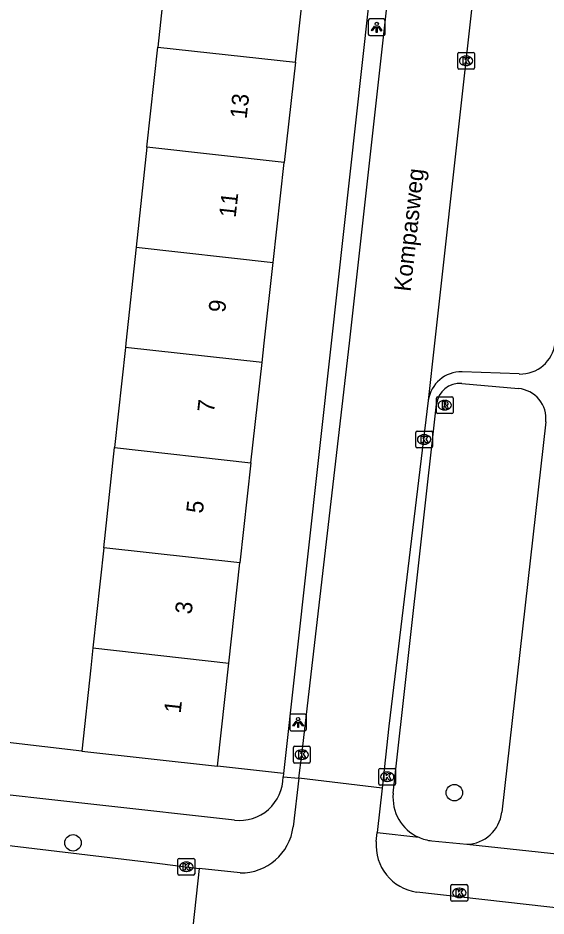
# Model space of a CAD drawing. Extents: x 161928 to 163055, y 386475 to 387428.
# Drawn here: x 162354.3 to 162385.7, y 386965.9 to 387019.4 of the extents above; entities that cross this region are included whole.
import ezdxf

# ---------------------------------------------------------------- set-up
doc = ezdxf.new("R2010")
doc.units = 0
for name, color, linetype in [('IMGEO_Boom', 7, 'Continuous'), ('IMGEO_Groenvoorziening', 7, 'Continuous'), ('IMGEO_Kolk', 7, 'Continuous'), ('IMGEO_Lichtpunt', 7, 'Continuous'), ('IMGEO_Openbare_ruimte_label', 7, 'Continuous'), ('IMGEO_Pand', 7, 'Continuous'), ('IMGEO_Pand_nummerreeks', 7, 'Continuous'), ('IMGEO_Rijbaan_lokaal_gesloten', 7, 'Continuous'), ('IMGEO_Rijbaan_lokaal_open', 7, 'Continuous'), ('IMGEO_Rioolput', 7, 'Continuous'), ('IMGEO_Voetpad_open', 7, 'Continuous')]:
    doc.layers.add(name, color=color, linetype=linetype)

msp = doc.modelspace()

# ---------------------------------------------------------------- linework, layer by layer
at = {"layer": 'IMGEO_Boom'}
for centre in [(162380.28, 386973.215), (162357.553, 386970.228)]:
    msp.add_circle(centre, 0.489, dxfattribs=at)
at = {"layer": 'IMGEO_Groenvoorziening'}
for points in [[(162358.078, 386975.691), (162351.103, 386976.499)], [(162370.099, 386974.362), (162366.155, 386974.797)]]:
    msp.add_lwpolyline(points, dxfattribs=at)
at = {"layer": 'IMGEO_Kolk'}
for p, q in [((162380.479, 387016.386), (162380.479, 387017.238)), ((162380.554, 387017.312), (162381.406, 387017.312)), ((162380.967, 387017.092), (162380.992, 387017.092)), ((162381.48, 387017.238), (162381.48, 387016.386)), ((162380.99, 387016.532), (162380.965, 387016.532)), ((162381.406, 387016.312), (162380.554, 387016.312)), ((162377.979, 386993.828), (162377.979, 386994.68)), ((162378.054, 386994.754), (162378.906, 386994.754)), ((162378.98, 386994.68), (162378.98, 386993.828)), ((162378.467, 386994.534), (162378.492, 386994.534)), ((162378.906, 386993.754), (162378.054, 386993.754)), ((162378.49, 386993.974), (162378.465, 386993.974)), ((162370.685, 386975.054), (162370.685, 386975.906)), ((162370.76, 386975.98), (162371.612, 386975.98)), ((162371.686, 386975.906), (162371.686, 386975.054)), ((162371.173, 386975.76), (162371.198, 386975.76)), ((162371.612, 386974.98), (162370.76, 386974.98)), ((162371.196, 386975.2), (162371.171, 386975.2)), ((162375.778, 386973.739), (162375.778, 386974.591)), ((162375.853, 386974.665), (162376.705, 386974.665)), ((162376.266, 386974.445), (162376.291, 386974.445)), ((162376.779, 386974.591), (162376.779, 386973.739)), ((162376.289, 386973.885), (162376.264, 386973.885)), ((162376.705, 386973.665), (162375.853, 386973.665)), ((162363.802, 386968.377), (162363.802, 386969.229)), ((162363.877, 386969.303), (162364.729, 386969.303)), ((162364.29, 386969.083), (162364.315, 386969.083)), ((162364.803, 386969.229), (162364.803, 386968.377)), ((162364.313, 386968.523), (162364.288, 386968.523)), ((162364.729, 386968.303), (162363.877, 386968.303)), ((162380.074, 386966.821), (162380.074, 386967.673)), ((162380.149, 386967.747), (162381.001, 386967.747)), ((162380.562, 386967.527), (162380.587, 386967.527)), ((162381.075, 386967.673), (162381.075, 386966.821)), ((162380.585, 386966.967), (162380.56, 386966.967)), ((162381.001, 386966.747), (162380.149, 386966.747))]:
    msp.add_line(p, q, dxfattribs=at)
for points in [[(162380.479, 387016.386), (162380.479, 387017.238)], [(162380.554, 387017.312), (162381.406, 387017.312)], [(162381.48, 387017.238), (162381.48, 387016.386)], [(162380.8, 387017.012), (162380.923, 387017.012), (162380.923, 387016.861), (162381.053, 387017.012), (162381.217, 387017.012), (162381.071, 387016.861), (162381.224, 387016.612), (162381.072, 387016.612), (162380.987, 387016.776), (162380.923, 387016.709), (162380.923, 387016.612), (162380.8, 387016.612), (162380.8, 387017.012)], [(162381.406, 387016.312), (162380.554, 387016.312)], [(162377.979, 386993.828), (162377.979, 386994.68)], [(162378.054, 386994.754), (162378.906, 386994.754)], [(162378.98, 386994.68), (162378.98, 386993.828)], [(162378.3, 386994.454), (162378.423, 386994.454), (162378.423, 386994.303), (162378.553, 386994.454), (162378.717, 386994.454), (162378.571, 386994.303), (162378.724, 386994.054), (162378.572, 386994.054), (162378.487, 386994.218), (162378.423, 386994.151), (162378.423, 386994.054), (162378.3, 386994.054), (162378.3, 386994.454)], [(162378.906, 386993.754), (162378.054, 386993.754)], [(162370.685, 386975.054), (162370.685, 386975.906)], [(162370.76, 386975.98), (162371.612, 386975.98)], [(162371.686, 386975.906), (162371.686, 386975.054)], [(162371.006, 386975.68), (162371.129, 386975.68), (162371.129, 386975.529), (162371.259, 386975.68), (162371.423, 386975.68), (162371.277, 386975.529), (162371.43, 386975.28), (162371.278, 386975.28), (162371.193, 386975.444), (162371.129, 386975.377), (162371.129, 386975.28), (162371.006, 386975.28), (162371.006, 386975.68)], [(162371.612, 386974.98), (162370.76, 386974.98)], [(162375.778, 386973.739), (162375.778, 386974.591)], [(162375.853, 386974.665), (162376.705, 386974.665)], [(162376.099, 386974.365), (162376.222, 386974.365), (162376.222, 386974.214), (162376.352, 386974.365), (162376.516, 386974.365), (162376.37, 386974.214), (162376.523, 386973.965), (162376.371, 386973.965), (162376.286, 386974.129), (162376.222, 386974.062), (162376.222, 386973.965), (162376.099, 386973.965), (162376.099, 386974.365)], [(162376.779, 386974.591), (162376.779, 386973.739)], [(162376.705, 386973.665), (162375.853, 386973.665)], [(162363.802, 386968.377), (162363.802, 386969.229)], [(162363.877, 386969.303), (162364.729, 386969.303)], [(162364.123, 386969.003), (162364.246, 386969.003), (162364.246, 386968.852), (162364.376, 386969.003), (162364.54, 386969.003), (162364.394, 386968.852), (162364.547, 386968.603), (162364.395, 386968.603), (162364.31, 386968.767), (162364.246, 386968.7), (162364.246, 386968.603), (162364.123, 386968.603), (162364.123, 386969.003)], [(162364.803, 386969.229), (162364.803, 386968.377)], [(162364.729, 386968.303), (162363.877, 386968.303)], [(162380.074, 386966.821), (162380.074, 386967.673)], [(162380.149, 386967.747), (162381.001, 386967.747)], [(162380.395, 386967.447), (162380.518, 386967.447), (162380.518, 386967.296), (162380.648, 386967.447), (162380.812, 386967.447), (162380.666, 386967.296), (162380.819, 386967.047), (162380.667, 386967.047), (162380.582, 386967.211), (162380.518, 386967.144), (162380.518, 386967.047), (162380.395, 386967.047), (162380.395, 386967.447)], [(162381.075, 386967.673), (162381.075, 386966.821)], [(162381.001, 386966.747), (162380.149, 386966.747)]]:
    msp.add_lwpolyline(points, dxfattribs=at)
for centre, start, end in [((162380.556, 387017.236), 91.552, 178.448), ((162380.556, 387017.236), 91.552, 178.448), ((162381.404, 387017.236), 1.552, 88.448), ((162381.404, 387017.236), 1.552, 88.448), ((162380.556, 387016.388), 181.552, 268.448), ((162380.556, 387016.388), 181.552, 268.448), ((162381.404, 387016.388), 271.552, 358.448), ((162381.404, 387016.388), 271.552, 358.448), ((162378.056, 386994.678), 91.552, 178.448), ((162378.056, 386994.678), 91.552, 178.448), ((162378.904, 386994.678), 1.552, 88.448), ((162378.904, 386994.678), 1.552, 88.448), ((162378.056, 386993.83), 181.552, 268.448), ((162378.056, 386993.83), 181.552, 268.448), ((162378.904, 386993.83), 271.552, 358.448), ((162378.904, 386993.83), 271.552, 358.448), ((162370.762, 386975.904), 91.552, 178.448), ((162370.762, 386975.904), 91.552, 178.448), ((162371.61, 386975.904), 1.552, 88.448), ((162371.61, 386975.904), 1.552, 88.448), ((162370.762, 386975.056), 181.552, 268.448), ((162370.762, 386975.056), 181.552, 268.448), ((162371.61, 386975.056), 271.552, 358.448), ((162371.61, 386975.056), 271.552, 358.448), ((162375.855, 386974.589), 91.552, 178.448), ((162375.855, 386974.589), 91.552, 178.448), ((162376.703, 386974.589), 1.552, 88.448), ((162376.703, 386974.589), 1.552, 88.448), ((162375.855, 386973.741), 181.552, 268.448), ((162375.855, 386973.741), 181.552, 268.448), ((162376.703, 386973.741), 271.552, 358.448), ((162376.703, 386973.741), 271.552, 358.448), ((162363.879, 386969.227), 91.552, 178.448), ((162363.879, 386969.227), 91.552, 178.448), ((162364.727, 386969.227), 1.552, 88.448), ((162364.727, 386969.227), 1.552, 88.448), ((162363.879, 386968.379), 181.552, 268.448), ((162363.879, 386968.379), 181.552, 268.448), ((162364.727, 386968.379), 271.552, 358.448), ((162364.727, 386968.379), 271.552, 358.448), ((162380.151, 386967.671), 91.552, 178.448), ((162380.151, 386967.671), 91.552, 178.448), ((162380.999, 386967.671), 1.552, 88.448), ((162380.999, 386967.671), 1.552, 88.448), ((162380.151, 386966.823), 181.552, 268.448), ((162380.151, 386966.823), 181.552, 268.448), ((162380.999, 386966.823), 271.552, 358.448), ((162380.999, 386966.823), 271.552, 358.448)]:
    msp.add_arc(centre, 0.0765, start, end, dxfattribs=at)
for centre, major_axis, ratio, start_param, end_param in [((162380.966, 387016.812), (-0.387, 0.002), 0.722429, 4.712389, 7.853982), ((162380.991, 387016.812), (-0.39, 0.002), 0.717154, 1.570796, 4.712389), ((162378.466, 386994.254), (-0.387, 0.002), 0.722429, 4.712389, 7.853982), ((162378.491, 386994.254), (-0.39, 0.002), 0.717154, 1.570796, 4.712389), ((162371.172, 386975.48), (-0.387, 0.002), 0.722429, 4.712389, 7.853982), ((162371.197, 386975.48), (-0.39, 0.002), 0.717154, 1.570796, 4.712389), ((162376.265, 386974.165), (-0.387, 0.002), 0.722429, 4.712389, 7.853982), ((162376.29, 386974.165), (-0.39, 0.002), 0.717154, 1.570796, 4.712389), ((162364.289, 386968.803), (-0.387, 0.002), 0.722429, 4.712389, 7.853982), ((162364.314, 386968.803), (-0.39, 0.002), 0.717154, 1.570796, 4.712389), ((162380.561, 386967.247), (-0.387, 0.002), 0.722429, 4.712389, 7.853982), ((162380.586, 386967.247), (-0.39, 0.002), 0.717154, 1.570796, 4.712389)]:
    msp.add_ellipse(centre, major_axis=major_axis, ratio=ratio, start_param=start_param, end_param=end_param, dxfattribs=at)
at = {"layer": 'IMGEO_Lichtpunt'}
for p, q in [((162375.153, 387019.213), (162375.153, 387018.406)), ((162375.153, 387019.213), (162375.153, 387018.406)), ((162376.055, 387019.308), (162375.247, 387019.308)), ((162376.055, 387019.308), (162375.247, 387019.308)), ((162376.149, 387018.406), (162376.149, 387019.213)), ((162376.149, 387018.406), (162376.149, 387019.213)), ((162375.247, 387018.312), (162376.055, 387018.312)), ((162375.247, 387018.312), (162376.055, 387018.312)), ((162370.469, 386977.804), (162370.469, 386976.997)), ((162370.469, 386977.804), (162370.469, 386976.997)), ((162371.371, 386977.899), (162370.563, 386977.899)), ((162371.371, 386977.899), (162370.563, 386977.899)), ((162371.465, 386976.997), (162371.465, 386977.804)), ((162371.465, 386976.997), (162371.465, 386977.804)), ((162370.563, 386976.903), (162371.371, 386976.903)), ((162370.563, 386976.903), (162371.371, 386976.903))]:
    msp.add_line(p, q, dxfattribs=at)
for points in [[(162375.527, 387018.877), (162375.566, 387018.849), (162375.378, 387018.587), (162375.34, 387018.614), (162375.527, 387018.877)], [(162375.629, 387018.829), (162375.676, 387018.829), (162375.676, 387018.507), (162375.629, 387018.507), (162375.629, 387018.829)], [(162375.739, 387018.849), (162375.777, 387018.876), (162375.964, 387018.614), (162375.925, 387018.586), (162375.739, 387018.849)], [(162370.843, 386977.468), (162370.882, 386977.44), (162370.694, 386977.178), (162370.656, 386977.205), (162370.843, 386977.468)], [(162371.055, 386977.44), (162371.093, 386977.467), (162371.28, 386977.205), (162371.241, 386977.177), (162371.055, 386977.44)], [(162370.945, 386977.42), (162370.992, 386977.42), (162370.992, 386977.098), (162370.945, 386977.098), (162370.945, 386977.42)]]:
    msp.add_lwpolyline(points, dxfattribs=at)
for centre in [(162375.652, 387019.011), (162370.968, 386977.602)]:
    msp.add_circle(centre, 0.0994, dxfattribs=at)
for centre, start, end in [((162375.247, 387019.213), 90, 180), ((162375.247, 387019.213), 90, 180), ((162376.055, 387019.213), 0, 90), ((162376.055, 387019.213), 0, 90), ((162375.247, 387018.406), 180, 270), ((162375.247, 387018.406), 180, 270), ((162376.055, 387018.406), 270, 0), ((162376.055, 387018.406), 270, 360), ((162370.563, 386977.804), 90, 180), ((162370.563, 386977.804), 90, 180), ((162371.371, 386977.804), 0, 90), ((162371.371, 386977.804), 0, 90), ((162370.563, 386976.997), 180, 270), ((162370.563, 386976.997), 180, 270), ((162371.371, 386976.997), 270, 0), ((162371.371, 386976.997), 270, 360)]:
    msp.add_arc(centre, 0.0946, start, end, dxfattribs=at)
at = {"layer": 'IMGEO_Pand'}
for points in [[(162363.246, 387023.597), (162362.603, 387017.632)], [(162370.808, 387016.722), (162371.469, 387022.685)], [(162361.959, 387011.667), (162362.603, 387017.632)], [(162362.603, 387017.632), (162370.808, 387016.722)], [(162370.808, 387016.722), (162370.146, 387010.759)], [(162361.959, 387011.667), (162361.315, 387005.701)], [(162370.146, 387010.759), (162361.959, 387011.667)], [(162369.484, 387004.795), (162370.146, 387010.759)], [(162361.315, 387005.701), (162360.7, 387000), (162360.672, 386999.736)], [(162361.315, 387005.701), (162369.484, 387004.795)], [(162368.822, 386998.832), (162368.952, 387000), (162369.484, 387004.795)], [(162360.672, 386999.736), (162360.028, 386993.77)], [(162368.822, 386998.832), (162360.672, 386999.736)], [(162368.16, 386992.868), (162368.822, 386998.832)], [(162359.384, 386987.805), (162360.028, 386993.77)], [(162360.028, 386993.77), (162368.16, 386992.868)], [(162368.16, 386992.868), (162367.499, 386986.905)], [(162359.384, 386987.805), (162358.741, 386981.839)], [(162367.499, 386986.905), (162359.384, 386987.805)], [(162366.837, 386980.941), (162367.499, 386986.905)], [(162358.741, 386981.839), (162358.614, 386980.663), (162358.078, 386975.691)], [(162358.741, 386981.839), (162366.837, 386980.941)], [(162366.155, 386974.797), (162366.837, 386980.941)], [(162358.078, 386975.691), (162366.155, 386974.797)]]:
    msp.add_lwpolyline(points, dxfattribs=at)
at = {"layer": 'IMGEO_Rijbaan_lokaal_gesloten'}
msp.add_lwpolyline([(162323.738, 386973.385), (162328.736, 386972.812), (162345.485, 386971.026), (162348.916, 386970.641), (162362.412, 386969.03), (162365.074, 386968.71)], dxfattribs=at)
at = {"layer": 'IMGEO_Rijbaan_lokaal_open'}
for points in [[(162371.02, 386974.085), (162371.186, 386975.48), (162374.021, 387000), (162378.678, 387041.833)], [(162382.527, 387030.958), (162379.106, 387000), (162378.727, 386996.574)], [(162378.727, 386996.574), (162376.384, 386977.172), (162375.974, 386973.494)], [(162371.02, 386974.085), (162370.675, 386971.181)], [(162375.974, 386973.494), (162371.02, 386974.085)], [(162375.974, 386973.494), (162375.678, 386970.841)], [(162375.619, 386970.31), (162375.678, 386970.841)], [(162365.074, 386968.71), (162364.207, 386960.846)], [(162367.512, 386968.436), (162365.074, 386968.71)], [(162399.005, 386964.936), (162378.037, 386967.289)]]:
    msp.add_lwpolyline(points, dxfattribs=at)
for centre, radius, start, end in [((162367.549, 386971.588), 3.152, 269.3218, 352.5841), ((162378.451, 386970.099), 2.84, 175.7374, 261.6099)]:
    msp.add_arc(centre, radius, start, end, dxfattribs=at)
at = {"layer": 'IMGEO_Rioolput'}
for p, q in [((162379.209, 386995.872), (162379.209, 386996.724)), ((162379.284, 386996.798), (162380.136, 386996.798)), ((162380.21, 386996.724), (162380.21, 386995.872)), ((162379.697, 386996.578), (162379.722, 386996.578)), ((162380.136, 386995.798), (162379.284, 386995.798)), ((162379.72, 386996.018), (162379.695, 386996.018))]:
    msp.add_line(p, q, dxfattribs=at)
for points in [[(162379.209, 386995.872), (162379.209, 386996.724)], [(162379.284, 386996.798), (162380.136, 386996.798)], [(162380.21, 386996.724), (162380.21, 386995.872)], [(162379.798, 386996.496), (162379.546, 386996.498), (162379.546, 386996.098)], [(162379.546, 386996.098), (162379.67, 386996.098), (162379.67, 386996.26), (162379.681, 386996.26)], [(162379.724, 386996.417), (162379.67, 386996.417), (162379.67, 386996.336)], [(162379.67, 386996.336), (162379.722, 386996.336)], [(162379.728, 386996.231), (162379.799, 386996.098), (162379.939, 386996.098), (162379.874, 386996.224)], [(162380.136, 386995.798), (162379.284, 386995.798)]]:
    msp.add_lwpolyline(points, dxfattribs=at)
for centre, radius, start, end in [((162379.286, 386996.722), 0.0765, 91.552, 178.448), ((162379.286, 386996.722), 0.0765, 91.552, 178.448), ((162380.134, 386996.722), 0.0765, 1.552, 88.448), ((162380.134, 386996.722), 0.0765, 1.552, 88.448), ((162379.68, 386996.207), 0.0533, 26.0293, 88.6989), ((162379.706, 386996.525), 0.19, 274.7715, 282.9687), ((162379.73, 386996.321), 0.0964, 77.0061, 93.1865), ((162379.744, 386996.378), 0.0378, 276.6634, 79.6772), ((162379.797, 386996.386), 0.109, 350.3612, 89.416), ((162379.795, 386996.386), 0.112, 277.5842, 350.9817), ((162379.779, 386996.171), 0.108, 29.5134, 73.7905), ((162379.286, 386995.874), 0.0765, 181.552, 268.448), ((162379.286, 386995.874), 0.0765, 181.552, 268.448), ((162380.134, 386995.874), 0.0765, 271.552, 358.448), ((162380.134, 386995.874), 0.0765, 271.552, 358.448)]:
    msp.add_arc(centre, radius, start, end, dxfattribs=at)
for centre, major_axis, ratio, start_param, end_param in [((162379.696, 386996.298), (-0.387, 0.002), 0.722429, 4.712389, 7.853982), ((162379.721, 386996.298), (-0.39, 0.002), 0.717154, 1.570796, 4.712389)]:
    msp.add_ellipse(centre, major_axis=major_axis, ratio=ratio, start_param=start_param, end_param=end_param, dxfattribs=at)
at = {"layer": 'IMGEO_Voetpad_open'}
for points in [[(162377.705, 387043.164), (162372.933, 387000), (162370.099, 386974.362)], [(162384.15, 386998.156), (162380.743, 386998.278)], [(162380.726, 386997.59), (162384.111, 386997.288)], [(162376.636, 386973.186), (162379.213, 386996.353)], [(162385.725, 386995.312), (162383.1, 386972.048)], [(162370.099, 386974.362), (162370.076, 386974.157)], [(162370.076, 386974.157), (162371.02, 386974.085)], [(162367.17, 386971.574), (162350.757, 386973.412)], [(162375.678, 386970.841), (162378.154, 386970.558)], [(162378.938, 386970.349), (162381.029, 386970.143)], [(162381.029, 386970.143), (162387.865, 386969.414)]]:
    msp.add_lwpolyline(points, dxfattribs=at)
for centre, radius, start, end in [((162384.221, 387000.227), 2.073, 268.0392, 353.7015), ((162380.674, 386996.315), 1.964, 87.9914, 172.4201), ((162380.601, 386996.199), 1.397, 84.88, 173.6575), ((162383.953, 386995.512), 1.783, 353.5645, 84.9195), ((162367.462, 386974.171), 2.614, 263.5786, 359.686), ((162379.204, 386972.917), 2.582, 174.02, 246.0036), ((162380.978, 386972.277), 2.134, 271.3714, 353.8472), ((162379.214, 386972.96), 2.626, 246.1846, 263.9617)]:
    msp.add_arc(centre, radius, start, end, dxfattribs=at)

# ---------------------------------------------------------------- texts
at = {"layer": 'IMGEO_Openbare_ruimte_label'}
msp.add_text('Kompasweg', height=1, rotation=83.6282, dxfattribs=at).set_placement((162377.668, 387003.034))
at = {"layer": 'IMGEO_Pand_nummerreeks'}
for s, rotation, p in [('13', 83.6676, (162367.895, 387013.321)), ('11', 83.6676, (162367.243, 387007.439)), ('9', 83.6676, (162366.614, 387001.785)), ('7', 83.6705, (162365.952, 386995.831)), ('5', 83.6705, (162365.286, 386989.823)), ('3', 83.6705, (162364.619, 386983.814)), ('1', 83.6705, (162363.966, 386977.918))]:
    msp.add_text(s, height=1, rotation=rotation, dxfattribs=at).set_placement(p)

doc.saveas('drawing.dxf')
